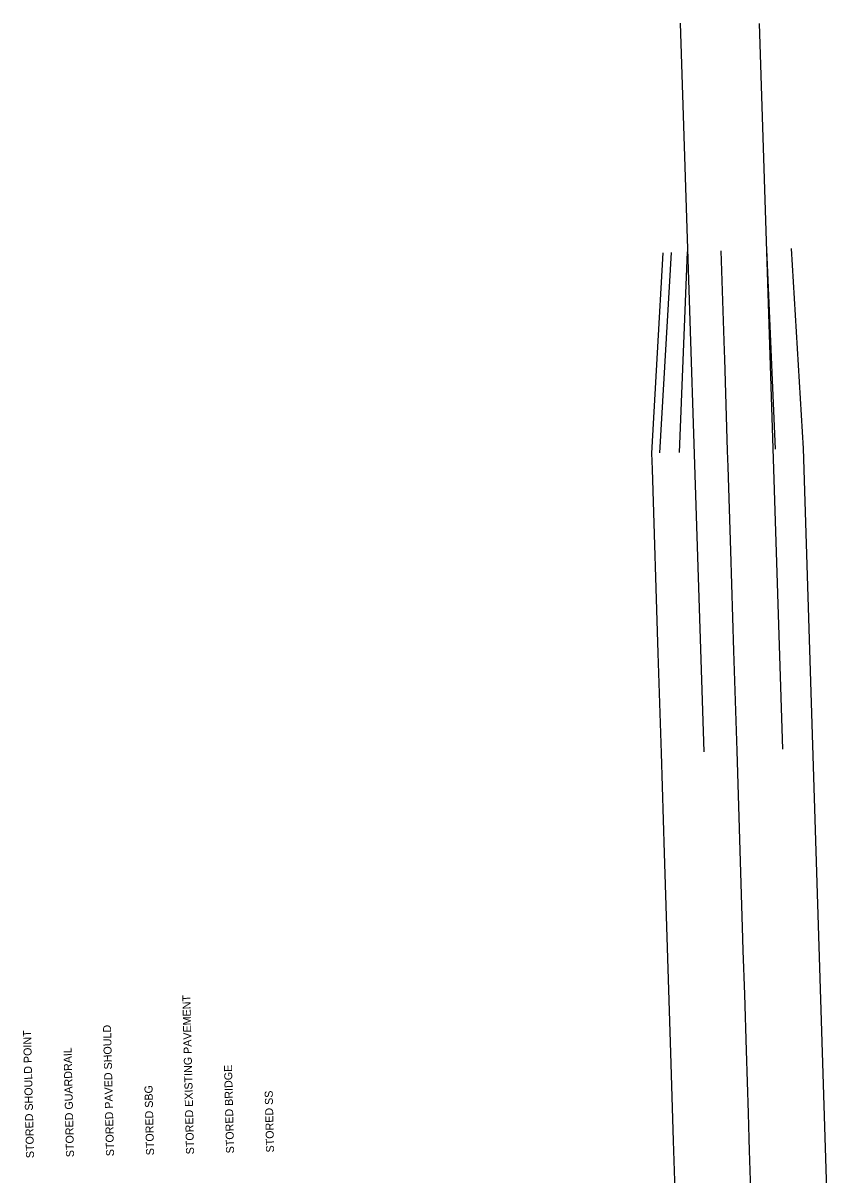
# Model space of a CAD drawing. Extents: x 2326474 to 2326697, y 123717 to 124767.
# Drawn here: x 2326474.5 to 2326676.6, y 124479.3 to 124767.3 of the extents above; entities that cross this region are included whole.
import ezdxf

# ---------------------------------------------------------------- set-up
doc = ezdxf.new("R2010")
doc.units = 0
for name, color, linetype in [('Cogo Default Point CELL', 7, 'Continuous'), ('COGO Default Point Elevation', 7, 'Continuous'), ('COGO Default Point Number', 7, 'Continuous'), ('CTL Supplemental Horizontal and Vertical CELL', 7, 'Continuous'), ('CTL Supplemental Horizontal and Vertical Cogo Elevation', 7, 'Continuous'), ('CTL Supplemental Horizontal and Vertical Cogo Number', 7, 'Continuous'), ('Exist Roads EOP Cogo Number', 7, 'Continuous'), ('Exist Roads EOP Cogo Point CELL', 7, 'Continuous'), ('Exist Structure Major Bridge WW Cogo Point CELL', 7, 'Continuous')]:
    doc.layers.add(name, color=color, linetype=linetype)

msp = doc.modelspace()

# ---------------------------------------------------------------- linework, layer by layer
at = {"layer": 'COGO Default Point Number'}
msp.add_line((2326636.39, 124709.91), (2326633.54, 124659.8), dxfattribs=at)
at = {"layer": 'CTL Supplemental Horizontal and Vertical CELL'}
for points in [[(2326638.69, 124767.28), (2326644.55, 124585.11)], [(2326664.34, 124585.73), (2326658.52, 124767.13)]]:
    msp.add_lwpolyline(points, dxfattribs=at)
at = {"layer": 'CTL Supplemental Horizontal and Vertical Cogo Elevation'}
for p, q in [((2326634.38, 124709.85), (2326632.96, 124684.79)), ((2326669.52, 124660.93), (2326666.5, 124710.92)), ((2326632.96, 124684.79), (2326631.54, 124659.73)), ((2326676.6, 124436.04), (2326669.52, 124660.93)), ((2326631.54, 124659.73), (2326631.66, 124655.73)), ((2326631.66, 124655.73), (2326633.11, 124609.76)), ((2326633.11, 124609.76), (2326633.9, 124584.77)), ((2326633.9, 124584.77), (2326634.69, 124559.78)), ((2326634.69, 124559.78), (2326636.26, 124509.81)), ((2326636.26, 124509.81), (2326636.95, 124487.82)), ((2326636.95, 124487.82), (2326638.15, 124449.84))]:
    msp.add_line(p, q, dxfattribs=at)
at = {"layer": 'Exist Roads EOP Cogo Number'}
for p, q in [((2326638.53, 124659.95), (2326640.53, 124710.04)), ((2326662.52, 124660.71), (2326660.33, 124710.66))]:
    msp.add_line(p, q, dxfattribs=at)
at = {"layer": 'Exist Structure Major Bridge WW Cogo Point CELL'}
msp.add_lwpolyline([(2326656.83, 124460.43), (2326656.04, 124485.42), (2326655.95, 124488.35), (2326655.94, 124488.42), (2326655.74, 124494.76), (2326655.25, 124510.41), (2326654.81, 124524.4), (2326654.46, 124535.39), (2326654.37, 124538.32), (2326654.37, 124538.39), (2326653.68, 124560.38), (2326652.89, 124585.37), (2326652.1, 124610.36), (2326651.31, 124635.34), (2326650.65, 124656.33), (2326650.53, 124660.33), (2326649.8, 124683.32), (2326649.74, 124685.32), (2326648.95, 124710.31)], dxfattribs=at)

# ---------------------------------------------------------------- texts
at = {"layer": 'Cogo Default Point CELL'}
msp.add_text('STORED BRIDGE', height=2, rotation=91.3572, dxfattribs=at).set_placement((2326527.22, 124484.73))
at = {"layer": 'COGO Default Point Elevation'}
msp.add_text('STORED SBG', height=2, rotation=91.3572, dxfattribs=at).set_placement((2326507.23, 124484.25))
at = {"layer": 'COGO Default Point Number'}
msp.add_text('STORED PAVED SHOULD', height=2, rotation=91.3572, dxfattribs=at).set_placement((2326497.23, 124484.02))
at = {"layer": 'CTL Supplemental Horizontal and Vertical CELL'}
msp.add_text('STORED EXISTING PAVEMENT', height=2, rotation=91.3572, dxfattribs=at).set_placement((2326517.22, 124484.49))
at = {"layer": 'CTL Supplemental Horizontal and Vertical Cogo Elevation'}
msp.add_text('STORED SHOULD POINT', height=2, rotation=91.3572, dxfattribs=at).set_placement((2326477.24, 124483.54))
at = {"layer": 'CTL Supplemental Horizontal and Vertical Cogo Number'}
msp.add_text('STORED GUARDRAIL', height=2, rotation=91.3572, dxfattribs=at).set_placement((2326487.23, 124483.78))
at = {"layer": 'Exist Roads EOP Cogo Point CELL'}
msp.add_text('STORED SS', height=2, rotation=91.3572, dxfattribs=at).set_placement((2326537.22, 124484.96))

doc.saveas('drawing.dxf')
